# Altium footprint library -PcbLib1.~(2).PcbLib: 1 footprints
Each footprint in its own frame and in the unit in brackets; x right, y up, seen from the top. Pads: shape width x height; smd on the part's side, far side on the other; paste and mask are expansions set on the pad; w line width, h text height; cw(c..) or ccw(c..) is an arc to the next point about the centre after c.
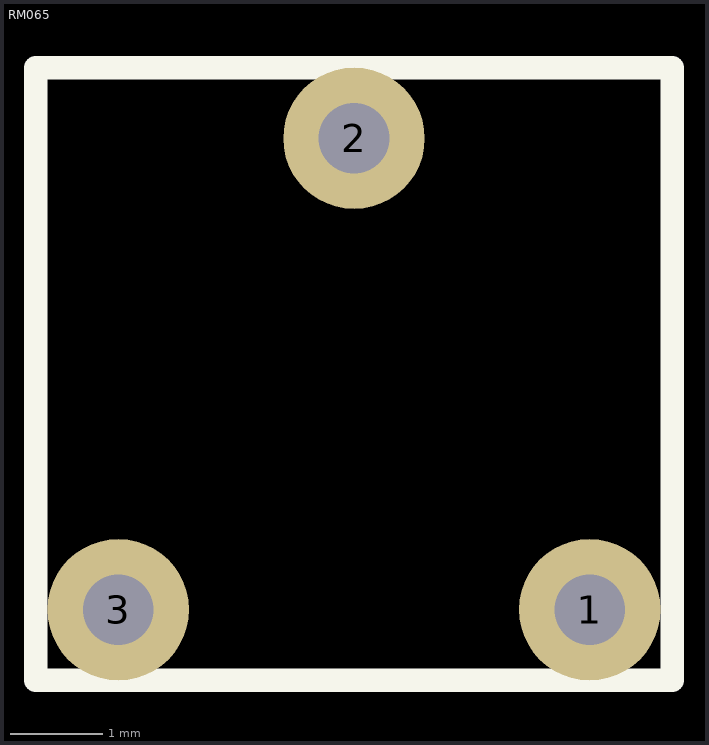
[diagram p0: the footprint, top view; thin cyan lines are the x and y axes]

## RM065 [mil]
pads (3):
  round 60 hole 30: 1(-32200,-34000) 2(-32300,-33800) 3(-32400,-34000)
Top Overlay:
  lines w10: -32435,-34030 -32165,-34030 -32165,-33770 -32435,-33770 -32435,-34030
